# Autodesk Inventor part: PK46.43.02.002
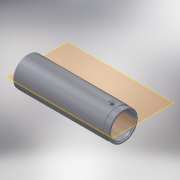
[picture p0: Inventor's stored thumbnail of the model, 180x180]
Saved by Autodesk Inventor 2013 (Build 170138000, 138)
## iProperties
Shininess: 64.0
Length Units: 11269
Angle Units: 11279
Time Units: 11290
Mass Units: 11283
Length Display Precision: 3
Angle Display Precision: 2
Compacted: True
Part Number: PK46.43.02.002
Document SubType Name: Modeling
Created: 2004-11
Material: Сталь высокопрочная низколегированная
Designer: ELarisa
Manufacturer: Standard
Standards Organization: Custom
Density: 7.84 g/cm^3
Mass: 46748.1 g
Surface Area: 7315.57 cm^2
Volume: 5962.77 cm^3
Density: 0.0
Volumn: 0.0
Area: 0.0
PropertySet Name: Model Information
Control State: 0
Master: False
Checked Out: False
Checked Out Date: 2008-10-09
Last Check In Date: 2008-10-09
Author: ELarisa
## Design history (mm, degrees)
sketch "Эскиз1"
  geometry: L1 (-125.155, -154.996)-(-125.155, -72.496); L2 (-119.878, -57.996)-(477.845, -57.996); L3 (477.845, -57.996)-(477.845, -61.496); L4 (477.845, -61.496)-(482.845, -61.496); L5 (484.345, -59.996)-(515.845, -59.996); L6 (515.845, -59.996)-(517.845, -61.996); L7 (517.845, -61.996)-(517.845, -154.996); L8 (517.845, -154.996)-(-125.155, -154.996); L9 (-125.155, -74.996)-(504.845, -74.996); L10 (504.845, -74.996)-(509.845, -73.656); L11 (-125.155, -72.496)-(-119.878, -57.996); L12 (482.845, -61.496)-(484.345, -59.996); L13 (509.845, -73.656)-(509.845, -68.996); L14 (509.845, -68.996)-(517.845, -68.996)
  constraints: 28 end point, 6 parallel, 3 perpendicular, 2 point on line, 1 vertical
  dimensions: "d0" = 643 distance of L7.end L1.start; "d2" = 5 horizontal distance of L9.end L10.end; "d3" = 15 deg angle of L10 L9; "d4" = 20 deg angle of L11 L1; "d6" = 45 deg angle of L5 L12; "d7" = 5 distance of L3.end L4.end; "d8" = 40 distance between parallel lines of L3 L7; "d9" = 2 horizontal distance of L5.end L6.end; "d10" = 2 horizontal distance of L5.end L6.end; "d11" = 97 distance between parallel lines of L8 L2; "d12" = 95 distance between parallel lines of L8 L5; "d13" = 93.5 distance between parallel lines of L8 L4; "d14" = 80 distance between parallel lines of L8 L9; "d15" = 8 distance of L13.end L14.end; "d16" = 86 distance between parallel lines of L8 L14; "d17" = 82.5 distance of L1.start L1.end
revolve "Вращение1" sketch "Эскиз1" stored, may be unused: angle "d18" = 90 deg
node "РабПлоскость1"
sketch "Эскиз2"
  geometry: L1 (477.845, -251.996)-(477.845, -57.996) reference; L2 (-119.878, -57.996)-(477.845, -57.996) reference; 1 further point
  dimensions: "d20" = 97 distance from line of L2 point (442.845, -154.996); "d21" = 35 distance from line of L1 point (442.845, -154.996)
hole "Отверстие1" sketch "Эскиз2" diameter "d22" = 25; stored, may be unused: countersink angle "d26" = 82 deg, drill point angle "d28" = 118 deg; dims "d23" = 6, "d24" = 42, "d25" = 5, "d27" = 25
body "Solid1"
other parameters: "d19" = 97
